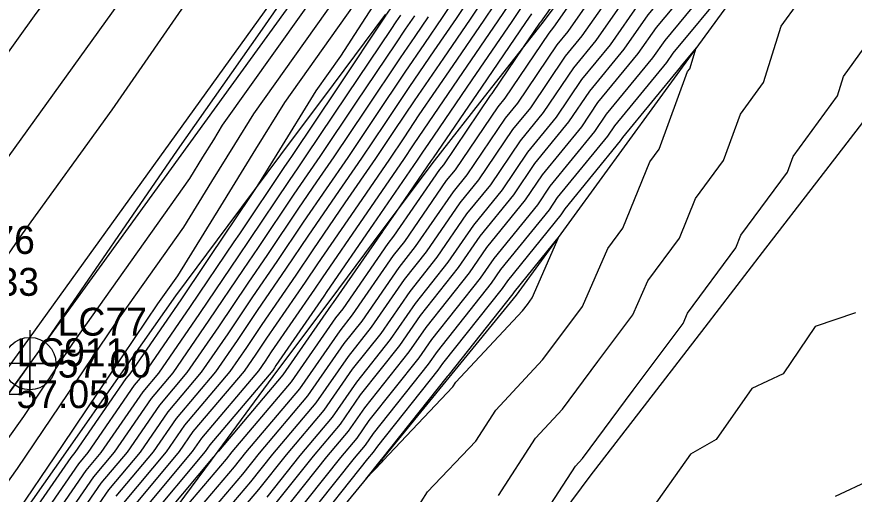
# Model space of a CAD drawing. Extents: x 2188792 to 2191981, y 386090 to 389710.
# Drawn here: x 2189855.4 to 2189930.5, y 387193.8 to 387236.6 of the extents above; entities that cross this region are included whole.
import ezdxf

# ---------------------------------------------------------------- set-up
doc = ezdxf.new("R2010")
doc.units = 0
for name, color, linetype in [('DTM Contours Major', 7, 'Continuous'), ('DTM Contours Minor', 7, 'Continuous'), ('Exist Roads EOP', 7, 'Continuous'), ('Exist Roads EOP Cogo Elevation', 7, 'Continuous'), ('Exist Roads EOP Cogo Number', 7, 'Continuous'), ('Exist Roads EOP Cogo Point CELL', 7, 'Continuous'), ('Exist Roads EOT', 7, 'Continuous'), ('Exist Roads EOT Cogo Elevation', 7, 'Continuous'), ('Exist Roads EOT Cogo Number', 7, 'Continuous'), ('Exist Roads EOT Cogo Point CELL', 7, 'Continuous'), ('PH Exist DTM Breakline', 7, 'Continuous')]:
    doc.layers.add(name, color=color, linetype=linetype)

msp = doc.modelspace()

# ---------------------------------------------------------------- linework, layer by layer
at = {"layer": 'DTM Contours Major'}
for points in [[(2189839.476, 387181.412), (2189856.598, 387205.434), (2189856.62, 387205.466), (2189856.64, 387205.496), (2189856.659, 387205.525), (2189858.223, 387207.732), (2189869.834, 387224.619), (2189877.249, 387235.156), (2189886.017, 387247.794), (2189890.656, 387253.898), (2189892.445, 387256.247), (2189909.424, 387278.537), (2189910.292, 387279.677), (2189910.315, 387279.709), (2189911.35, 387281.066), (2189927.816, 387303.457), (2189927.931, 387303.631), (2189928.041, 387303.798), (2189928.147, 387303.957), (2189928.3, 387304.131), (2189939.5, 387319.43), (2189939.713, 387319.861), (2189939.829, 387320.314), (2189949.954, 387334.279)], [(2189917.132, 387279.855), (2189913.608, 387274.538), (2189909.682, 387268.615), (2189905.738, 387263.266), (2189902.224, 387257.833), (2189898.241, 387251.676), (2189897.783, 387251.057), (2189893.47, 387244.344), (2189889.481, 387238.133), (2189888.58, 387236.778), (2189888.553, 387236.739), (2189888.523, 387236.696), (2189884.166, 387230.195), (2189880.109, 387224.142), (2189879.776, 387223.659), (2189879.425, 387223.149), (2189875.383, 387217.13), (2189874.875, 387216.393), (2189870.987, 387210.609), (2189866.85, 387204.603), (2189865.971, 387203.564), (2189861.814, 387197.539), (2189860.959, 387196.518), (2189856.786, 387190.476)], [(2189932.804, 387267.819), (2189929.756, 387263.274), (2189926.201, 387260.157), (2189923.014, 387255.523), (2189920.979, 387253.109), (2189917.789, 387248.498), (2189915.758, 387246.064), (2189912.565, 387241.471), (2189910.536, 387239.021), (2189907.341, 387234.445), (2189905.314, 387231.979), (2189902.622, 387227.985), (2189900.541, 387225.436), (2189897.877, 387221.518), (2189895.75, 387218.898), (2189893.094, 387215.036), (2189890.652, 387211.962), (2189888.058, 387208.207), (2189885.5, 387204.992), (2189882.969, 387201.342), (2189879.583, 387197.342), (2189877.107, 387194.231), (2189873.571, 387190.068)], [(2189897.532, 387240.507), (2189894.809, 387236.412), (2189892.815, 387233.499), (2189890.636, 387230.317), (2189888.412, 387226.998), (2189886.34, 387223.908), (2189884.002, 387220.511), (2189881.533, 387216.925), (2189879.589, 387214.031), (2189876.981, 387210.245), (2189875.174, 387207.557), (2189873.252, 387204.766), (2189869.725, 387200.594), (2189867.656, 387197.595), (2189864.328, 387193.621)], [(2189919.1, 387239.163), (2189914.242, 387233.296), (2189913.665, 387232.469), (2189908.996, 387226.79), (2189908.373, 387225.865), (2189903.877, 387220.359), (2189903.141, 387219.276), (2189898.791, 387213.918), (2189897.95, 387212.696), (2189893.103, 387206.595), (2189892.317, 387205.457), (2189887.377, 387199.247), (2189886.645, 387198.192), (2189885.666, 387197.035), (2189880.736, 387190.842)], [(2189904.352, 387201.418), (2189907.523, 387205.678), (2189910.636, 387209.857), (2189911.978, 387212.906), (2189914.819, 387216.739), (2189916.256, 387220.274), (2189918.762, 387223.674), (2189920.281, 387227.841), (2189922.362, 387230.684), (2189923.929, 387235.705), (2189925.452, 387237.807)], [(2189901.553, 387236.819), (2189901.039, 387236.046), (2189897.077, 387230.259), (2189892.749, 387223.938), (2189892.658, 387223.801), (2189892.572, 387223.674), (2189889.392, 387219.054), (2189888.237, 387217.376), (2189888.201, 387217.329), (2189883.799, 387210.957), (2189883.624, 387210.737), (2189879.294, 387204.492), (2189873.5, 387197.649), (2189873.478, 387197.621), (2189873.046, 387197.113), (2189867.697, 387190.725)], [(2189898.605, 387193.697), (2189901.931, 387198.824), (2189904.352, 387201.418)]]:
    msp.add_lwpolyline(points, dxfattribs=at)
at = {"layer": 'DTM Contours Minor'}
for points in [[(2189806.103, 387171.079), (2189818.83, 387185.769), (2189823.977, 387192.841), (2189832.146, 387202.524), (2189840.636, 387214.199), (2189849.542, 387226.21), (2189857.019, 387236.627), (2189863.862, 387245.866), (2189872.906, 387258.466), (2189874.441, 387260.833), (2189883.298, 387274.48), (2189889.961, 387284.755), (2189894.836, 387292.266), (2189899.699, 387299.764), (2189911.601, 387317.434), (2189912.049, 387318.099), (2189914.929, 387322.013), (2189928.336, 387339.246)], [(2189937.835, 387325.802), (2189928.451, 387313.821), (2189924.705, 387308.455), (2189912.794, 387292.052), (2189906.641, 387284.303), (2189906.065, 387283.51), (2189895.672, 387270.72), (2189887.112, 387259.916), (2189885.216, 387257.522), (2189881.384, 387252.787), (2189871.553, 387239.191), (2189863.95, 387228.232), (2189855.914, 387217.121), (2189849.603, 387208.007), (2189840.533, 387195.387), (2189832.223, 387183.387), (2189825.819, 387174.474), (2189818.869, 387164.423), (2189809.4, 387152.406)], [(2189849.089, 387187.083), (2189855.514, 387196.097), (2189858.561, 387200.607), (2189861.481, 387204.929), (2189864.282, 387209.076), (2189870.405, 387217.719), (2189872.925, 387221.801), (2189874.972, 387225.117), (2189876.668, 387227.865), (2189886.895, 387242.237), (2189888.817, 387245.23), (2189890.642, 387248.071), (2189892.222, 387250.529), (2189894.767, 387253.972), (2189896.249, 387256.263), (2189897.556, 387258.284), (2189910.059, 387275.238), (2189911.623, 387277.599), (2189913.027, 387279.718), (2189914.163, 387281.453), (2189926.879, 387298.745), (2189928.163, 387300.687), (2189929.39, 387302.543), (2189930.564, 387304.318)], [(2189854.972, 387191.429), (2189859.531, 387198.177), (2189863.901, 387204.646), (2189868.093, 387210.851), (2189869.874, 387213.364), (2189873.73, 387219.611), (2189876.862, 387224.686), (2189879.457, 387228.89), (2189885.676, 387237.63), (2189888.707, 387242.349), (2189891.585, 387246.828), (2189894.076, 387250.705), (2189895.925, 387253.206), (2189898.24, 387256.786), (2189900.284, 387259.945), (2189909.933, 387273.03), (2189912.284, 387276.578), (2189914.395, 387279.764), (2189916.102, 387282.372), (2189926.411, 387296.39), (2189928.279, 387299.215), (2189930.064, 387301.916), (2189931.772, 387304.499)], [(2189915.764, 387279.809), (2189912.946, 387275.558), (2189909.808, 387270.823), (2189903.011, 387261.605), (2189900.232, 387257.31), (2189897.083, 387252.441), (2189895.929, 387250.881), (2189892.528, 387245.586), (2189888.597, 387239.468), (2189884.457, 387233.023), (2189882.247, 387229.916), (2189878.752, 387224.255), (2189876.959, 387221.35), (2189874.542, 387217.75), (2189874.454, 387217.622), (2189870.15, 387211.219), (2189865.569, 387204.571), (2189865.22, 387204.158), (2189860.646, 387197.528), (2189860.285, 387197.097), (2189855.717, 387190.484)], [(2189844.282, 387184.248), (2189856.056, 387200.766), (2189857.59, 387203.036), (2189859.06, 387205.212), (2189860.471, 387207.3), (2189870.937, 387222.073), (2189872.12, 387223.99), (2189873.082, 387225.548), (2189873.878, 387226.839), (2189888.114, 387246.845), (2189888.927, 387248.111), (2189889.699, 387249.313), (2189890.368, 387250.353), (2189893.609, 387254.737), (2189894.257, 387255.739), (2189894.829, 387256.623), (2189910.184, 387277.446), (2189910.961, 387278.619)], [(2189930.927, 387271.181), (2189930.198, 387270.89), (2189925.73, 387264.228), (2189924.679, 387263.307), (2189920.19, 387256.779), (2189919.473, 387255.928), (2189915.078, 387249.574), (2189914.264, 387248.599), (2189909.951, 387242.395), (2189909.053, 387241.31), (2189904.811, 387235.235), (2189903.841, 387234.055), (2189900.322, 387228.832), (2189899.206, 387227.466), (2189895.772, 387222.415), (2189894.534, 387220.89), (2189891.151, 387215.972), (2189889.671, 387214.109), (2189886.355, 387209.307), (2189884.75, 387207.29), (2189881.499, 387202.602), (2189877.15, 387197.465), (2189875.655, 387195.587), (2189871.093, 387190.216)], [(2189931.501, 387269.354), (2189927.743, 387263.751), (2189925.44, 387261.732), (2189921.602, 387256.151), (2189920.226, 387254.518), (2189916.434, 387249.036), (2189915.011, 387247.331), (2189911.258, 387241.933), (2189909.795, 387240.166), (2189906.076, 387234.84), (2189904.578, 387233.017), (2189901.472, 387228.409), (2189899.874, 387226.451), (2189896.825, 387221.967), (2189895.142, 387219.894), (2189892.123, 387215.504), (2189890.162, 387213.036), (2189887.207, 387208.757), (2189885.125, 387206.141), (2189882.234, 387201.972), (2189878.366, 387197.403), (2189876.381, 387194.909), (2189872.332, 387190.142)], [(2189931.769, 387262.797), (2189926.961, 387258.582), (2189924.426, 387254.896), (2189921.732, 387251.7), (2189919.145, 387247.959), (2189916.504, 387244.796), (2189913.872, 387241.01), (2189911.277, 387237.876), (2189908.606, 387234.05), (2189906.051, 387230.941), (2189903.772, 387227.561), (2189901.208, 387224.42), (2189898.93, 387221.07), (2189896.358, 387217.902), (2189894.065, 387214.568), (2189891.142, 387210.889), (2189888.91, 387207.657), (2189885.876, 387203.843), (2189883.704, 387200.712), (2189880.8, 387197.28), (2189877.833, 387193.554)], [(2189896.966, 387216.906), (2189899.983, 387220.621), (2189901.875, 387223.405), (2189904.923, 387227.137), (2189906.787, 387229.904), (2189909.871, 387233.654), (2189912.018, 387236.731), (2189915.179, 387240.548), (2189917.251, 387243.529), (2189920.501, 387247.421), (2189922.486, 387250.291), (2189925.839, 387254.268), (2189927.722, 387257.007), (2189933.782, 387262.319)], [(2189897.574, 387215.91), (2189901.035, 387220.173), (2189902.543, 387222.39), (2189906.073, 387226.713), (2189907.523, 387228.866), (2189911.135, 387233.259), (2189912.76, 387235.586), (2189916.486, 387240.086), (2189917.998, 387242.261), (2189921.856, 387246.883), (2189923.239, 387248.881), (2189927.251, 387253.641), (2189928.483, 387255.432), (2189935.796, 387261.842)], [(2189937.809, 387261.365), (2189929.243, 387253.857), (2189928.663, 387253.013), (2189923.992, 387247.472), (2189923.212, 387246.344), (2189918.745, 387240.994), (2189917.793, 387239.625), (2189913.501, 387234.441), (2189912.4, 387232.864), (2189908.26, 387227.828), (2189907.223, 387226.289), (2189903.21, 387221.375), (2189902.088, 387219.725), (2189898.183, 387214.914), (2189896.979, 387213.164), (2189892.613, 387207.669), (2189891.465, 387206.007), (2189887.001, 387200.396), (2189885.91, 387198.822), (2189884.449, 387197.096), (2189880.01, 387191.52)], [(2189907.352, 387243.159), (2189902.357, 387236.081), (2189902.285, 387235.972), (2189900.824, 387233.838), (2189898.022, 387229.68), (2189897.872, 387229.497), (2189893.666, 387223.312), (2189893.317, 387222.882), (2189889.209, 387216.908), (2189888.691, 387216.256), (2189884.651, 387210.407), (2189883.999, 387209.588), (2189880.029, 387203.862), (2189874.717, 387197.587), (2189874.204, 387196.943), (2189868.615, 387190.364)], [(2189908.312, 387242.455), (2189903.547, 387235.63), (2189903.105, 387235.092), (2189899.172, 387229.256), (2189898.539, 387228.481), (2189894.719, 387222.863), (2189893.926, 387221.886), (2189890.18, 387216.44), (2189889.181, 387215.182), (2189885.503, 387209.857), (2189884.375, 387208.439), (2189880.764, 387203.232), (2189875.933, 387197.526), (2189874.929, 387196.265), (2189869.854, 387190.29)], [(2189896.728, 387241.245), (2189893.563, 387236.485), (2189891.962, 387234.147), (2189890.214, 387231.593), (2189887.563, 387227.638), (2189885.094, 387223.955), (2189883.157, 387221.141), (2189881.111, 387218.17), (2189878.748, 387214.651), (2189876.56, 387211.474), (2189874.337, 387208.167), (2189871.971, 387204.734), (2189868.974, 387201.188), (2189866.488, 387197.584), (2189863.654, 387194.201), (2189861.061, 387190.446)], [(2189898.336, 387239.769), (2189896.055, 387236.339), (2189893.667, 387232.851), (2189891.059, 387229.041), (2189889.261, 387226.359), (2189887.587, 387223.861), (2189884.847, 387219.882), (2189881.955, 387215.68), (2189880.431, 387213.411), (2189877.402, 387209.015), (2189876.012, 387206.946), (2189874.532, 387204.799), (2189870.476, 387200), (2189868.824, 387197.607), (2189865.002, 387193.042)], [(2189899.141, 387239.032), (2189897.301, 387236.265), (2189894.52, 387232.203), (2189891.481, 387227.765), (2189890.11, 387225.719), (2189888.833, 387223.814), (2189885.692, 387219.252), (2189882.376, 387214.436), (2189881.272, 387212.791), (2189877.823, 387207.785), (2189876.849, 387206.336), (2189875.812, 387204.831), (2189871.226, 387199.406), (2189869.993, 387197.618), (2189865.676, 387192.463)], [(2189899.945, 387238.294), (2189898.547, 387236.192), (2189895.372, 387231.555), (2189891.904, 387226.489), (2189890.959, 387225.08), (2189890.079, 387223.767), (2189886.537, 387218.622), (2189882.798, 387213.191), (2189882.113, 387212.171), (2189878.244, 387206.556), (2189877.686, 387205.726), (2189877.093, 387204.864), (2189871.977, 387198.812), (2189871.161, 387197.629), (2189866.35, 387191.883)], [(2189900.749, 387237.556), (2189899.793, 387236.119), (2189896.224, 387230.907), (2189892.327, 387225.214), (2189891.808, 387224.44), (2189891.326, 387223.721), (2189887.383, 387217.993), (2189883.219, 387211.946), (2189882.954, 387211.551), (2189878.666, 387205.326), (2189878.524, 387205.115), (2189878.373, 387204.896), (2189872.728, 387198.218), (2189872.33, 387197.641), (2189867.024, 387191.304)], [(2189889.825, 387236.705), (2189889.405, 387236.091), (2189888.946, 387235.42), (2189885.015, 387229.556), (2189881.355, 387224.095), (2189880.621, 387223.03), (2189879.846, 387221.904), (2189876.224, 387216.51), (2189875.296, 387215.163), (2189871.825, 387209.998), (2189868.13, 387204.636), (2189866.722, 387202.97), (2189862.983, 387197.55), (2189861.633, 387195.938), (2189857.854, 387190.468)], [(2189891.071, 387236.631), (2189890.258, 387235.443), (2189889.369, 387234.144), (2189885.864, 387228.916), (2189882.601, 387224.048), (2189881.466, 387222.4), (2189880.268, 387220.66), (2189877.066, 387215.89), (2189875.717, 387213.934), (2189872.662, 387209.388), (2189869.411, 387204.668), (2189867.473, 387202.376), (2189864.151, 387197.562), (2189862.307, 387195.359), (2189858.923, 387190.461)], [(2189892.317, 387236.558), (2189891.11, 387234.795), (2189889.791, 387232.869), (2189886.713, 387228.277), (2189883.848, 387224.002), (2189882.311, 387221.77), (2189880.69, 387219.415), (2189877.907, 387215.271), (2189876.139, 387212.704), (2189873.5, 387208.777), (2189870.691, 387204.701), (2189868.223, 387201.782), (2189865.319, 387197.573), (2189862.981, 387194.78), (2189859.992, 387190.453)], [(2189906.146, 387197.014), (2189910.688, 387203.113), (2189915.145, 387209.099), (2189915.551, 387210.02), (2189919.879, 387215.86), (2189920.337, 387216.987), (2189924.507, 387222.644), (2189925.015, 387224.039), (2189928.983, 387229.461), (2189929.532, 387231.218), (2189933.235, 387236.328)], [(2189902.557, 387205.823), (2189904.359, 387208.242), (2189906.126, 387210.616), (2189908.406, 387215.792), (2189909.76, 387217.619), (2189912.174, 387223.561), (2189913.017, 387224.704), (2189915.546, 387231.643), (2189915.74, 387231.908), (2189916.32, 387233.765), (2189914.984, 387232.151), (2189914.93, 387232.074), (2189909.733, 387225.752), (2189909.523, 387225.441), (2189904.545, 387219.344), (2189904.194, 387218.828), (2189899.399, 387212.922), (2189898.922, 387212.228), (2189893.593, 387205.522), (2189893.169, 387204.907), (2189887.752, 387198.098), (2189887.38, 387197.561), (2189886.882, 387196.974), (2189881.462, 387190.164)], [(2189878.559, 387192.876), (2189882.016, 387197.219), (2189884.44, 387200.082), (2189886.251, 387202.694), (2189889.762, 387207.107), (2189891.632, 387209.815), (2189895.036, 387214.1), (2189896.966, 387216.906)], [(2189904.057, 387216.914), (2189900.007, 387211.926), (2189899.893, 387211.76), (2189894.084, 387204.448), (2189894.021, 387204.357), (2189888.127, 387196.949), (2189888.115, 387196.931), (2189888.099, 387196.912), (2189886.697, 387195.152), (2189888.218, 387196.729), (2189888.274, 387196.816), (2189894.524, 387203.415), (2189894.791, 387203.826), (2189900.763, 387210.227), (2189901.194, 387210.806), (2189901.617, 387211.374), (2189904.057, 387216.914)], [(2189879.285, 387192.198), (2189883.233, 387197.158), (2189885.175, 387199.452), (2189886.626, 387201.545), (2189890.614, 387206.557), (2189892.123, 387208.742), (2189896.008, 387213.632), (2189897.574, 387215.91)], [(2189930.614, 387210.033), (2189926.999, 387208.835), (2189924.107, 387204.58), (2189921.32, 387203.277), (2189918.126, 387198.691), (2189915.825, 387197.379), (2189912.421, 387192.573)], [(2189890.549, 387191.333), (2189892.254, 387194.005), (2189896.565, 387198.556), (2189898.361, 387201.325), (2189902.557, 387205.823)], [(2189900.646, 387188.838), (2189905.502, 387196.323), (2189906.146, 387197.014)], [(2189936.345, 387192.59), (2189931.982, 387195.089), (2189928.769, 387193.586)]]:
    msp.add_lwpolyline(points, dxfattribs=at)
at = {"layer": 'Exist Roads EOP'}
msp.add_lwpolyline([(2190335.128, 387868.989), (2190306.373, 387829.271), (2190274.581, 387784.921), (2190245.133, 387744.071), (2190214.553, 387701.741), (2190184.89, 387660.475), (2190157.493, 387622.204), (2190126.048, 387578.501), (2190091.216, 387530.568), (2190059.634, 387486.726), (2190026.932, 387441.783), (2189997.689, 387401.032), (2189957.023, 387344.154), (2189927.908, 387303.922), (2189889.008, 387250.224), (2189856.606, 387205.5), (2189825.68, 387162.612), (2189795.668, 387120.822), (2189765.955, 387079.619), (2189734.998, 387036.704), (2189703.849, 386993.356), (2189673.984, 386951.979), (2189643.253, 386909.427)], dxfattribs=at)
at = {"layer": 'Exist Roads EOP Cogo Point CELL'}
msp.add_lwpolyline([(2189856.606, 387208.5), (2189856.606, 387202.5), (2189856.606, 387205.5), (2189859.606, 387205.5), (2189853.606, 387205.5)], dxfattribs=at)
msp.add_circle((2189856.606, 387205.5), 2.344, dxfattribs=at)
at = {"layer": 'Exist Roads EOT'}
for points in [[(2190174.375, 387667.889), (2190147.471, 387630.495), (2190115.247, 387585.778), (2190081.202, 387538.232), (2190049.502, 387494.256), (2190017.538, 387450.182), (2189987.334, 387408.357), (2189946.666, 387352.019), (2189917.402, 387311.129), (2189878.955, 387257.772), (2189846.565, 387212.819), (2189815.837, 387170.306), (2189785.374, 387128.351), (2189755.717, 387086.921), (2189724.953, 387044.041), (2189693.727, 387000.805), (2189663.933, 386959.217), (2189633.425, 386917.196)], [(2189989.253, 387391.986), (2189958.581, 387349.453), (2189928.09, 387307.216), (2189909.67, 387281.603), (2189884.44, 387246.513), (2189852.91, 387202.766), (2189821.507, 387159.305), (2189790.01, 387115.85), (2189759.16, 387072.957), (2189728.247, 387029.91), (2189696.407, 386985.689), (2189665.45, 386942.736), (2189635.049, 386900.502)]]:
    msp.add_lwpolyline(points, dxfattribs=at)
at = {"layer": 'Exist Roads EOT Cogo Point CELL'}
msp.add_lwpolyline([(2189852.91, 387205.766), (2189852.91, 387199.766), (2189852.91, 387202.766), (2189849.91, 387202.766), (2189855.91, 387202.766)], dxfattribs=at)
at = {"layer": 'PH Exist DTM Breakline'}
for points in [[(2189963.399, 387314.577), (2189958.981, 387307.188), (2189954.532, 387301.885), (2189950.082, 387296.583), (2189944.919, 387290.386), (2189939.756, 387284.189), (2189934.592, 387277.992), (2189929.429, 387271.796), (2189924.041, 387264.629), (2189918.653, 387257.462), (2189913.265, 387250.294), (2189907.877, 387243.127), (2189902.489, 387235.96), (2189897.664, 387229.812), (2189892.84, 387223.664), (2189888.163, 387217.412), (2189883.486, 387211.159), (2189878.809, 387204.907), (2189873.445, 387197.651), (2189868.08, 387190.396)], [(2189950.259, 387270.147), (2189944.33, 387265.686), (2189938.4, 387261.225), (2189929.921, 387252.454), (2189924.967, 387245.647), (2189920.013, 387238.84), (2189915.06, 387232.033), (2189910.106, 387225.227), (2189905.152, 387218.42), (2189900.198, 387211.613), (2189894.169, 387204.262), (2189888.14, 387196.91), (2189882.11, 387189.559), (2189876.646, 387182.203), (2189871.181, 387174.848), (2189865.716, 387167.492), (2189860.251, 387160.136), (2189855.22, 387153.995), (2189850.188, 387147.855), (2189846.875, 387141.948), (2189843.562, 387136.041), (2189840.249, 387130.133), (2189836.712, 387120.427)], [(2189960.26, 387260.146), (2189951.23, 387250.918), (2189946.719, 387245.772), (2189942.209, 387240.626), (2189937.699, 387235.48), (2189932.549, 387228.803), (2189927.398, 387222.125), (2189922.248, 387215.448), (2189917.098, 387208.77), (2189911.947, 387202.093), (2189906.797, 387195.416), (2189901.099, 387187.757), (2189895.401, 387180.099), (2189889.704, 387172.441), (2189884.006, 387164.783), (2189877.49, 387154.418), (2189869.666, 387143.667), (2189864.812, 387135.283), (2189859.958, 387126.899), (2189855.104, 387118.515), (2189850.25, 387110.131)], [(2189888.495, 387236.783), (2189883.785, 387230.482), (2189879.075, 387224.181), (2189874.366, 387217.88), (2189869.656, 387211.579), (2189864.725, 387204.549), (2189859.794, 387197.519), (2189854.863, 387190.49), (2189849.932, 387183.46), (2189844.544, 387175.116), (2189839.156, 387166.772), (2189833.698, 387158.46), (2189828.24, 387150.149), (2189823.03, 387143.525), (2189817.819, 387136.902), (2189809.372, 387127.264), (2189805.132, 387120.57), (2189803.345, 387115.661), (2189803.11, 387109.54), (2189802.322, 387100.55)]]:
    msp.add_lwpolyline(points, dxfattribs=at)

# ---------------------------------------------------------------- texts
at = {"layer": 'Exist Roads EOP Cogo Elevation'}
msp.add_text('57.00', height=2.5, dxfattribs=at).set_placement((2189859.106, 387204.25))
at = {"layer": 'Exist Roads EOP Cogo Number'}
msp.add_text('LC77', height=2.5, dxfattribs=at).set_placement((2189859.106, 387208))
at = {"layer": 'Exist Roads EOT Cogo Elevation'}
for s, p in [('57.33', (2189849.065, 387211.569)), ('57.05', (2189855.41, 387201.516))]:
    msp.add_text(s, height=2.5, dxfattribs=at).set_placement(p)
at = {"layer": 'Exist Roads EOT Cogo Number'}
for s, p in [('LC76', (2189849.065, 387215.319)), ('LC911', (2189855.41, 387205.266))]:
    msp.add_text(s, height=2.5, dxfattribs=at).set_placement(p)

doc.saveas('drawing.dxf')
